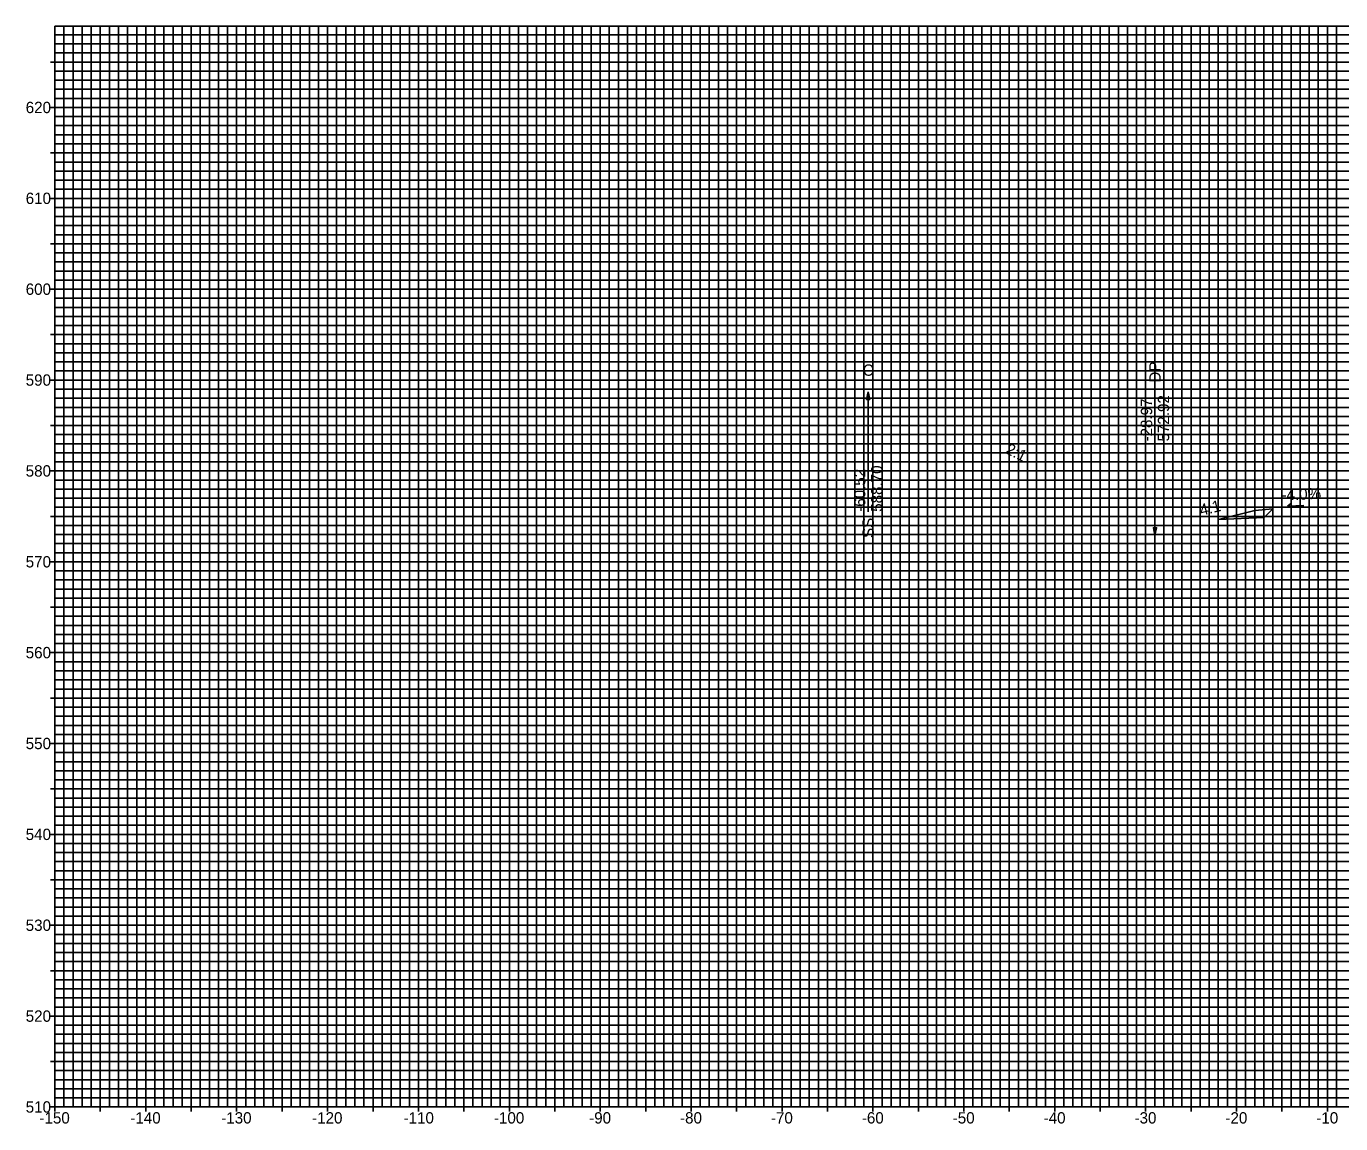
# Model space of a CAD drawing. Extents: x -153 to 153, y 508 to 629.
# Drawn here: x -153.1 to -8.5, y 508.2 to 628.9 of the extents above; entities that cross this region are included whole.
import ezdxf

# ---------------------------------------------------------------- set-up
doc = ezdxf.new("R2010")
doc.units = 0
for name, color, linetype in [('E_NCDOT_XS_Center_Line_Elevation_Label', 7, 'Continuous'), ('Level_63', 7, 'Continuous'), ('P_NCDOT_XS_Label_Grade_Point', 7, 'Continuous'), ('P_NCDOT_XS_Label_Slope_Superelevation', 7, 'Continuous'), ('P_NCDOT_XS_Sheet_Annotation_Label', 7, 'Continuous'), ('P_NCDOT_XS_Sheet_Grid_Border', 7, 'Continuous'), ('Prop XS Grade Point', 7, 'Continuous'), ('Scratch_Level_3', 7, 'Continuous'), ('Scratch_Level_4', 7, 'Continuous'), ('Sheet_Grid_Major', 7, 'Continuous'), ('Sheet_Grid_Middle', 7, 'Continuous'), ('Sheet_Grid_Minor', 7, 'Continuous')]:
    doc.layers.add(name, color=color, linetype=linetype)

msp = doc.modelspace()

# ---------------------------------------------------------------- linework, layer by layer
at = {"layer": 'E_NCDOT_XS_Center_Line_Elevation_Label'}
for p, q in [((-14.4, 576.13), (-14.07, 576.38)), ((-12.6, 576.2), (-14.4, 576.13))]:
    msp.add_line(p, q, dxfattribs=at)
at = {"layer": 'Level_63'}
msp.add_line((-11, 576.02), (-11, 576.65), dxfattribs=at)
at = {"layer": 'P_NCDOT_XS_Label_Grade_Point'}
for p, q in [((-60.52, 588.7), (-60.52, 575.5)), ((-60.52, 588.7), (-60.52, 575.5)), ((-28.97, 572.92), (-28.97, 588.52))]:
    msp.add_line(p, q, dxfattribs=at)
for points in [[(-60.52, 588.7), (-60.34, 587.88), (-60.7, 587.88)], [(-60.52, 588.7), (-60.34, 587.88), (-60.7, 587.88)], [(-28.97, 572.92), (-29.14, 573.74), (-28.79, 573.74)]]:
    msp.add_lwpolyline(points, close=True, dxfattribs=at)
at = {"layer": 'P_NCDOT_XS_Sheet_Grid_Border'}
for p, q in [((-150, 628.94), (150, 628.94)), ((-150, 510), (-150, 628.94)), ((-150, 510), (150, 510))]:
    msp.add_line(p, q, dxfattribs=at)
at = {"layer": 'Scratch_Level_3'}
msp.add_line((-21.98, 574.67), (-16.95, 574.87), dxfattribs=at)
at = {"layer": 'Scratch_Level_4'}
msp.add_lwpolyline([(-21.98, 574.67), (-16.95, 574.87), (-16, 575.82), (-18, 575.66)], close=True, dxfattribs=at)
at = {"layer": 'Sheet_Grid_Major'}
for p, q in [((-140, 510), (-140, 628.94)), ((-130, 510), (-130, 628.94)), ((-120, 510), (-120, 628.94)), ((-110, 510), (-110, 628.94)), ((-100, 510), (-100, 628.94)), ((-90, 510), (-90, 628.94)), ((-80, 510), (-80, 628.94)), ((-70, 510), (-70, 628.94)), ((-60, 510), (-60, 628.94)), ((-50, 510), (-50, 628.94)), ((-40, 510), (-40, 628.94)), ((-30, 510), (-30, 628.94)), ((-20, 510), (-20, 628.94)), ((-10, 510), (-10, 628.94)), ((-150, 620), (150, 620)), ((-150, 610), (150, 610)), ((-150, 600), (150, 600)), ((-150, 590), (150, 590)), ((-150, 580), (150, 580)), ((-150, 570), (150, 570)), ((-150, 560), (150, 560)), ((-150, 550), (150, 550)), ((-150, 540), (150, 540)), ((-150, 530), (150, 530)), ((-150, 520), (150, 520))]:
    msp.add_line(p, q, dxfattribs=at)
at = {"layer": 'Sheet_Grid_Middle'}
for p, q in [((-145, 510), (-145, 628.94)), ((-140, 510), (-140, 628.94)), ((-135, 510), (-135, 628.94)), ((-130, 510), (-130, 628.94)), ((-125, 510), (-125, 628.94)), ((-120, 510), (-120, 628.94)), ((-115, 510), (-115, 628.94)), ((-110, 510), (-110, 628.94)), ((-105, 510), (-105, 628.94)), ((-100, 510), (-100, 628.94)), ((-95, 510), (-95, 628.94)), ((-90, 510), (-90, 628.94)), ((-85, 510), (-85, 628.94)), ((-80, 510), (-80, 628.94)), ((-75, 510), (-75, 628.94)), ((-70, 510), (-70, 628.94)), ((-65, 510), (-65, 628.94)), ((-60, 510), (-60, 628.94)), ((-55, 510), (-55, 628.94)), ((-50, 510), (-50, 628.94)), ((-45, 510), (-45, 628.94)), ((-40, 510), (-40, 628.94)), ((-35, 510), (-35, 628.94)), ((-30, 510), (-30, 628.94)), ((-25, 510), (-25, 628.94)), ((-20, 510), (-20, 628.94)), ((-15, 510), (-15, 628.94)), ((-10, 510), (-10, 628.94)), ((-150, 625), (-150.48, 625)), ((-150, 625), (150, 625)), ((-150, 620), (-150.48, 620)), ((-150, 620), (150, 620)), ((-150, 615), (-150.48, 615)), ((-150, 615), (150, 615)), ((-150, 610), (-150.48, 610)), ((-150, 610), (150, 610)), ((-150, 605), (-150.48, 605)), ((-150, 605), (150, 605)), ((-150, 600), (-150.48, 600)), ((-150, 600), (150, 600)), ((-150, 595), (-150.48, 595)), ((-150, 595), (150, 595)), ((-150, 590), (-150.48, 590)), ((-150, 590), (150, 590)), ((-150, 585), (-150.48, 585)), ((-150, 585), (150, 585)), ((-150, 580), (-150.48, 580)), ((-150, 580), (150, 580)), ((-150, 575), (-150.48, 575)), ((-150, 575), (150, 575)), ((-150, 570), (-150.48, 570)), ((-150, 570), (150, 570)), ((-150, 565), (-150.48, 565)), ((-150, 565), (150, 565)), ((-150, 560), (-150.48, 560)), ((-150, 560), (150, 560)), ((-150, 555), (-150.48, 555)), ((-150, 555), (150, 555)), ((-150, 550), (-150.48, 550)), ((-150, 550), (150, 550)), ((-150, 545), (-150.48, 545)), ((-150, 545), (150, 545)), ((-150, 540), (-150.48, 540)), ((-150, 540), (150, 540)), ((-150, 535), (-150.48, 535)), ((-150, 535), (150, 535)), ((-150, 530), (-150.48, 530)), ((-150, 530), (150, 530)), ((-150, 525), (-150.48, 525)), ((-150, 525), (150, 525)), ((-150, 520), (-150.48, 520)), ((-150, 520), (150, 520)), ((-150, 515), (-150.48, 515)), ((-150, 515), (150, 515)), ((-150, 510), (-150.48, 510)), ((-150, 510), (-150, 509.52)), ((-145, 510), (-145, 509.52)), ((-140, 510), (-140, 509.52)), ((-135, 510), (-135, 509.52)), ((-130, 510), (-130, 509.52)), ((-125, 510), (-125, 509.52)), ((-120, 510), (-120, 509.52)), ((-115, 510), (-115, 509.52)), ((-110, 510), (-110, 509.52)), ((-105, 510), (-105, 509.52)), ((-100, 510), (-100, 509.52)), ((-95, 510), (-95, 509.52)), ((-90, 510), (-90, 509.52)), ((-85, 510), (-85, 509.52)), ((-80, 510), (-80, 509.52)), ((-75, 510), (-75, 509.52)), ((-70, 510), (-70, 509.52)), ((-65, 510), (-65, 509.52)), ((-60, 510), (-60, 509.52)), ((-55, 510), (-55, 509.52)), ((-50, 510), (-50, 509.52)), ((-45, 510), (-45, 509.52)), ((-40, 510), (-40, 509.52)), ((-35, 510), (-35, 509.52)), ((-30, 510), (-30, 509.52)), ((-25, 510), (-25, 509.52)), ((-20, 510), (-20, 509.52)), ((-15, 510), (-15, 509.52)), ((-10, 510), (-10, 509.52))]:
    msp.add_line(p, q, dxfattribs=at)
at = {"layer": 'Sheet_Grid_Minor'}
for p, q in [((-150, 628), (150, 628)), ((-149, 510), (-149, 628.94)), ((-148, 510), (-148, 628.94)), ((-147, 510), (-147, 628.94)), ((-146, 510), (-146, 628.94)), ((-144, 510), (-144, 628.94)), ((-143, 510), (-143, 628.94)), ((-142, 510), (-142, 628.94)), ((-141, 510), (-141, 628.94)), ((-139, 510), (-139, 628.94)), ((-138, 510), (-138, 628.94)), ((-137, 510), (-137, 628.94)), ((-136, 510), (-136, 628.94)), ((-134, 510), (-134, 628.94)), ((-133, 510), (-133, 628.94)), ((-132, 510), (-132, 628.94)), ((-131, 510), (-131, 628.94)), ((-129, 510), (-129, 628.94)), ((-128, 510), (-128, 628.94)), ((-127, 510), (-127, 628.94)), ((-126, 510), (-126, 628.94)), ((-124, 510), (-124, 628.94)), ((-123, 510), (-123, 628.94)), ((-122, 510), (-122, 628.94)), ((-121, 510), (-121, 628.94)), ((-119, 510), (-119, 628.94)), ((-118, 510), (-118, 628.94)), ((-117, 510), (-117, 628.94)), ((-116, 510), (-116, 628.94)), ((-114, 510), (-114, 628.94)), ((-113, 510), (-113, 628.94)), ((-112, 510), (-112, 628.94)), ((-111, 510), (-111, 628.94)), ((-109, 510), (-109, 628.94)), ((-108, 510), (-108, 628.94)), ((-107, 510), (-107, 628.94)), ((-106, 510), (-106, 628.94)), ((-104, 510), (-104, 628.94)), ((-103, 510), (-103, 628.94)), ((-102, 510), (-102, 628.94)), ((-101, 510), (-101, 628.94)), ((-99, 510), (-99, 628.94)), ((-98, 510), (-98, 628.94)), ((-97, 510), (-97, 628.94)), ((-96, 510), (-96, 628.94)), ((-94, 510), (-94, 628.94)), ((-93, 510), (-93, 628.94)), ((-92, 510), (-92, 628.94)), ((-91, 510), (-91, 628.94)), ((-89, 510), (-89, 628.94)), ((-88, 510), (-88, 628.94)), ((-87, 510), (-87, 628.94)), ((-86, 510), (-86, 628.94)), ((-84, 510), (-84, 628.94)), ((-83, 510), (-83, 628.94)), ((-82, 510), (-82, 628.94)), ((-81, 510), (-81, 628.94)), ((-79, 510), (-79, 628.94)), ((-78, 510), (-78, 628.94)), ((-77, 510), (-77, 628.94)), ((-76, 510), (-76, 628.94)), ((-74, 510), (-74, 628.94)), ((-73, 510), (-73, 628.94)), ((-72, 510), (-72, 628.94)), ((-71, 510), (-71, 628.94)), ((-69, 510), (-69, 628.94)), ((-68, 510), (-68, 628.94)), ((-67, 510), (-67, 628.94)), ((-66, 510), (-66, 628.94)), ((-64, 510), (-64, 628.94)), ((-63, 510), (-63, 628.94)), ((-62, 510), (-62, 628.94)), ((-61, 510), (-61, 628.94)), ((-59, 510), (-59, 628.94)), ((-58, 510), (-58, 628.94)), ((-57, 510), (-57, 628.94)), ((-56, 510), (-56, 628.94)), ((-54, 510), (-54, 628.94)), ((-53, 510), (-53, 628.94)), ((-52, 510), (-52, 628.94)), ((-51, 510), (-51, 628.94)), ((-49, 510), (-49, 628.94)), ((-48, 510), (-48, 628.94)), ((-47, 510), (-47, 628.94)), ((-46, 510), (-46, 628.94)), ((-44, 510), (-44, 628.94)), ((-43, 510), (-43, 628.94)), ((-42, 510), (-42, 628.94)), ((-41, 510), (-41, 628.94)), ((-39, 510), (-39, 628.94)), ((-38, 510), (-38, 628.94)), ((-37, 510), (-37, 628.94)), ((-36, 510), (-36, 628.94)), ((-34, 510), (-34, 628.94)), ((-33, 510), (-33, 628.94)), ((-32, 510), (-32, 628.94)), ((-31, 510), (-31, 628.94)), ((-29, 510), (-29, 628.94)), ((-28, 510), (-28, 628.94)), ((-27, 510), (-27, 628.94)), ((-26, 510), (-26, 628.94)), ((-24, 510), (-24, 628.94)), ((-23, 510), (-23, 628.94)), ((-22, 510), (-22, 628.94)), ((-21, 510), (-21, 628.94)), ((-19, 510), (-19, 628.94)), ((-18, 510), (-18, 628.94)), ((-17, 510), (-17, 628.94)), ((-16, 510), (-16, 628.94)), ((-14, 510), (-14, 628.94)), ((-13, 510), (-13, 628.94)), ((-12, 510), (-12, 628.94)), ((-11, 510), (-11, 628.94)), ((-9, 510), (-9, 628.94)), ((-150, 627), (150, 627)), ((-150, 626), (150, 626)), ((-150, 624), (150, 624)), ((-150, 623), (150, 623)), ((-150, 622), (150, 622)), ((-150, 621), (150, 621)), ((-150, 619), (150, 619)), ((-150, 618), (150, 618)), ((-150, 617), (150, 617)), ((-150, 616), (150, 616)), ((-150, 614), (150, 614)), ((-150, 613), (150, 613)), ((-150, 612), (150, 612)), ((-150, 611), (150, 611)), ((-150, 609), (150, 609)), ((-150, 608), (150, 608)), ((-150, 607), (150, 607)), ((-150, 606), (150, 606)), ((-150, 604), (150, 604)), ((-150, 603), (150, 603)), ((-150, 602), (150, 602)), ((-150, 601), (150, 601)), ((-150, 599), (150, 599)), ((-150, 598), (150, 598)), ((-150, 597), (150, 597)), ((-150, 596), (150, 596)), ((-150, 594), (150, 594)), ((-150, 593), (150, 593)), ((-150, 592), (150, 592)), ((-150, 591), (150, 591)), ((-150, 589), (150, 589)), ((-150, 588), (150, 588)), ((-150, 587), (150, 587)), ((-150, 586), (150, 586)), ((-150, 584), (150, 584)), ((-150, 583), (150, 583)), ((-150, 582), (150, 582)), ((-150, 581), (150, 581)), ((-150, 579), (150, 579)), ((-150, 578), (150, 578)), ((-150, 577), (150, 577)), ((-150, 576), (150, 576)), ((-150, 574), (150, 574)), ((-150, 573), (150, 573)), ((-150, 572), (150, 572)), ((-150, 571), (150, 571)), ((-150, 569), (150, 569)), ((-150, 568), (150, 568)), ((-150, 567), (150, 567)), ((-150, 566), (150, 566)), ((-150, 564), (150, 564)), ((-150, 563), (150, 563)), ((-150, 562), (150, 562)), ((-150, 561), (150, 561)), ((-150, 559), (150, 559)), ((-150, 558), (150, 558)), ((-150, 557), (150, 557)), ((-150, 556), (150, 556)), ((-150, 554), (150, 554)), ((-150, 553), (150, 553)), ((-150, 552), (150, 552)), ((-150, 551), (150, 551)), ((-150, 549), (150, 549)), ((-150, 548), (150, 548)), ((-150, 547), (150, 547)), ((-150, 546), (150, 546)), ((-150, 544), (150, 544)), ((-150, 543), (150, 543)), ((-150, 542), (150, 542)), ((-150, 541), (150, 541)), ((-150, 539), (150, 539)), ((-150, 538), (150, 538)), ((-150, 537), (150, 537)), ((-150, 536), (150, 536)), ((-150, 534), (150, 534)), ((-150, 533), (150, 533)), ((-150, 532), (150, 532)), ((-150, 531), (150, 531)), ((-150, 529), (150, 529)), ((-150, 528), (150, 528)), ((-150, 527), (150, 527)), ((-150, 526), (150, 526)), ((-150, 524), (150, 524)), ((-150, 523), (150, 523)), ((-150, 522), (150, 522)), ((-150, 521), (150, 521)), ((-150, 519), (150, 519)), ((-150, 518), (150, 518)), ((-150, 517), (150, 517)), ((-150, 516), (150, 516)), ((-150, 514), (150, 514)), ((-150, 513), (150, 513)), ((-150, 512), (150, 512)), ((-150, 511), (150, 511))]:
    msp.add_line(p, q, dxfattribs=at)

# ---------------------------------------------------------------- texts
at = {"layer": 'P_NCDOT_XS_Label_Slope_Superelevation'}
for s, rotation, p in [('2:1', 333.4349, (-45.53, 582)), ('-4.0%', 2.2906, (-15.03, 576.74)), ('4:1', 14.0362, (-23.88, 575.05)), ('4:1', 14.0362, (-23.88, 575.05))]:
    msp.add_text(s, height=1.248, rotation=rotation, dxfattribs=at).set_placement(p)
at = {"layer": 'P_NCDOT_XS_Sheet_Annotation_Label'}
for s, p in [('620', (-153.21, 619.38)), ('610', (-153.21, 609.38)), ('600', (-153.21, 599.38)), ('590', (-153.21, 589.38)), ('580', (-153.21, 579.38)), ('570', (-153.21, 569.38)), ('560', (-153.21, 559.38)), ('550', (-153.21, 549.38)), ('540', (-153.21, 539.38)), ('530', (-153.21, 529.38)), ('520', (-153.21, 519.38)), ('510', (-153.21, 509.38)), ('-150', (-151.7, 508.18)), ('-140', (-141.7, 508.18)), ('-130', (-131.7, 508.18)), ('-120', (-121.7, 508.18)), ('-110', (-111.64, 508.18)), ('-100', (-101.7, 508.18)), ('-90', (-91.22, 508.18)), ('-80', (-81.22, 508.18)), ('-70', (-71.22, 508.18)), ('-60', (-61.22, 508.18)), ('-50', (-51.22, 508.18)), ('-40', (-41.22, 508.18)), ('-30', (-31.22, 508.18)), ('-20', (-21.22, 508.18)), ('-10', (-11.22, 508.18))]:
    msp.add_text(s, height=1.248, dxfattribs=at).set_placement(p)
at = {"layer": 'Prop XS Grade Point'}
msp.add_text('C', height=1.25, dxfattribs=at).set_placement((-61.12, 590.47))
msp.add_text('C', height=1.25, dxfattribs=at).set_placement((-61.12, 590.47))
for s, p in [('DP', (-28.34, 589.72)), ('-28.97', (-29.28, 583.24)), ('572.92', (-27.41, 583.24)), ('-60.52', (-60.83, 575.5)), ('-60.52', (-60.83, 575.5)), ('588.70', (-58.96, 575.5)), ('588.70', (-58.96, 575.5)), ('SS', (-59.9, 572.62)), ('SS', (-59.9, 572.62))]:
    msp.add_text(s, height=1.248, rotation=90, dxfattribs=at).set_placement(p)

doc.saveas('drawing.dxf')
